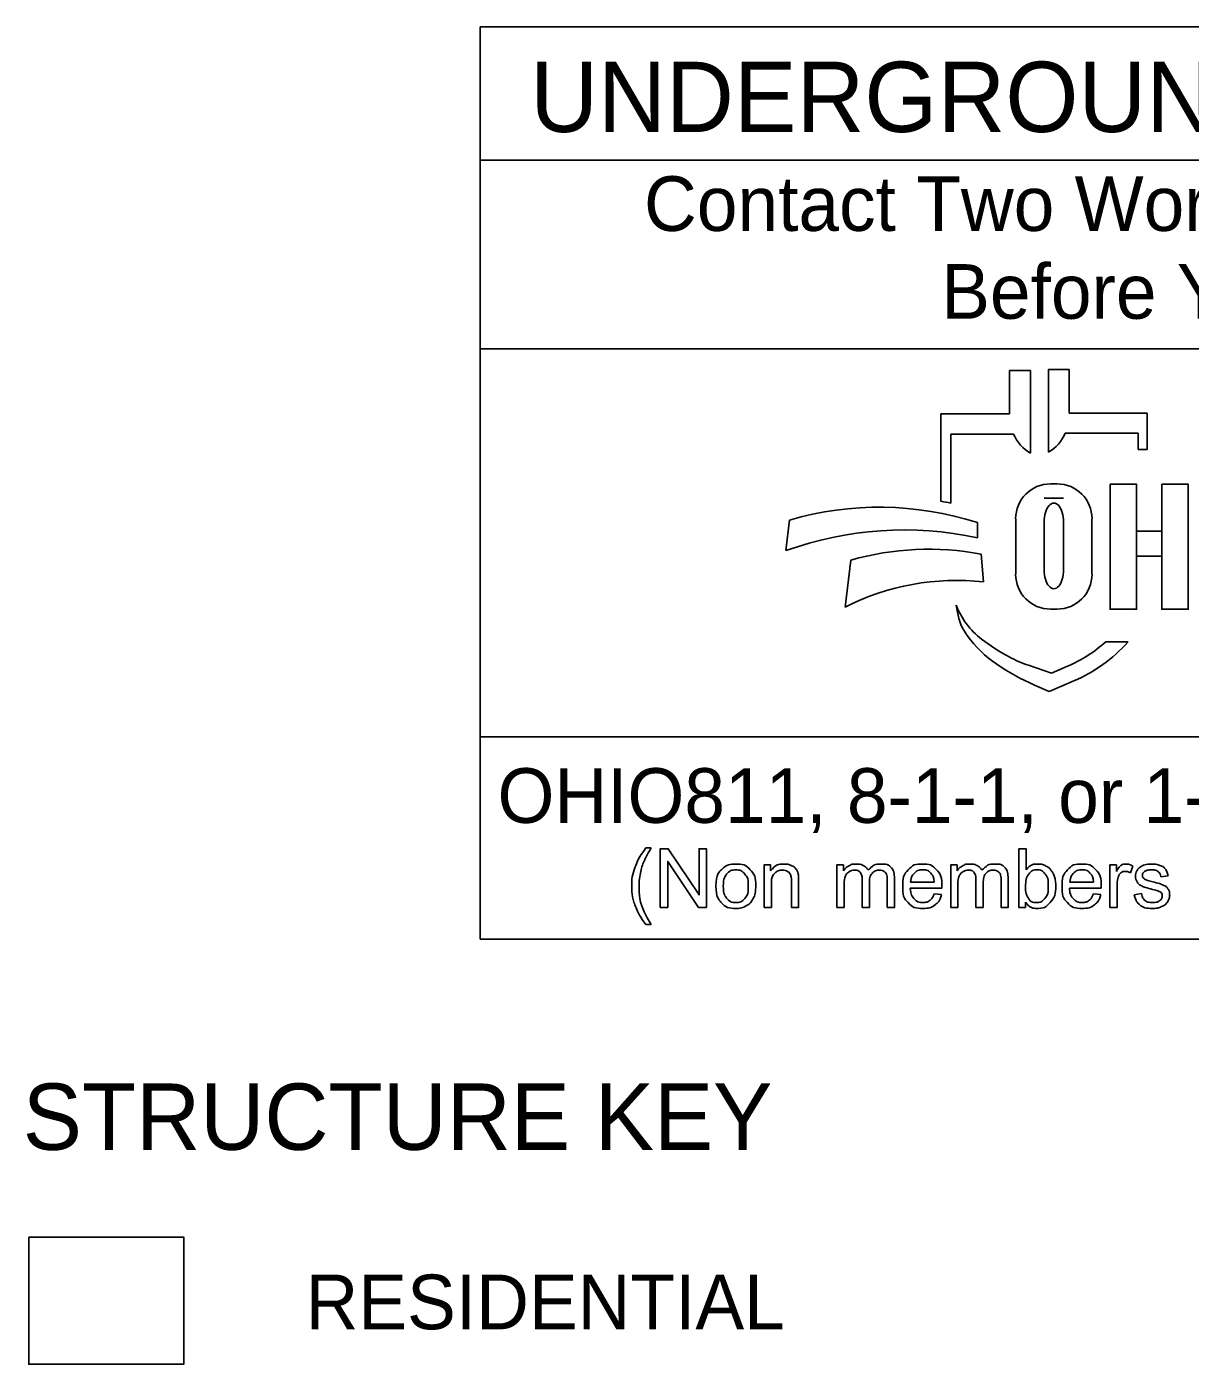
# Model space of a CAD drawing. Extents: x -8.8 to 41.4, y 0 to 34.6.
# Drawn here: x 20.008 to 22.988, y 5.453 to 8.88 of the extents above; entities that cross this region are included whole.
import ezdxf

# ---------------------------------------------------------------- set-up
doc = ezdxf.new("R2010")
doc.units = 0
doc.layers.add('SH_Border', color=7, linetype='Continuous')
doc.layers.add('SH_Data', color=7, linetype='Continuous')

msp = doc.modelspace()

# ---------------------------------------------------------------- linework, layer by layer
at = {"layer": 'SH_Border'}
for p, q in [((21.1696, 6.5424), (21.1696, 8.8799)), ((25.4196, 8.8799), (21.1696, 8.8799)), ((21.1696, 8.5383), (25.4196, 8.5383)), ((21.1696, 8.055), (25.4196, 8.055)), ((25.4196, 7.0603), (21.1696, 7.0603)), ((25.4196, 6.5424), (21.1696, 6.5424))]:
    msp.add_line(p, q, dxfattribs=at)
at = {"layer": 'SH_Data'}
for p, q in [((22.5256, 7.8879), (22.5256, 7.9994)), ((22.5256, 7.9994), (22.5793, 7.9994)), ((22.5793, 7.9994), (22.5793, 7.7873)), ((22.625, 7.7897), (22.625, 8.0017)), ((22.625, 8.0017), (22.6786, 8.0017)), ((22.6786, 8.0017), (22.6786, 7.8902)), ((22.3497, 7.664), (22.3497, 7.8879)), ((22.3497, 7.8879), (22.5256, 7.8879)), ((22.6786, 7.8902), (22.8778, 7.8902)), ((22.8778, 7.8902), (22.8778, 7.7964)), ((22.3749, 7.8365), (22.3749, 7.6596)), ((22.536, 7.8365), (22.3749, 7.8365)), ((22.8545, 7.8388), (22.6682, 7.8388)), ((22.8545, 7.7964), (22.8545, 7.8388)), ((22.8778, 7.7964), (22.8545, 7.7964)), ((22.6306, 7.7087), (22.6472, 7.7087)), ((22.6639, 7.6717), (22.6141, 7.6717)), ((21.9523, 7.5377), (21.9617, 7.6159)), ((22.443, 7.6094), (22.443, 7.5705)), ((22.5412, 7.4773), (22.5412, 7.6193)), ((22.6141, 7.4886), (22.6141, 7.611)), ((22.6639, 7.611), (22.6639, 7.4886)), ((22.7366, 7.6193), (22.7366, 7.4773)), ((22.1041, 7.3932), (22.1188, 7.5133)), ((22.4529, 7.5288), (22.4592, 7.4578)), ((22.3918, 7.3803), (22.3888, 7.3982)), ((22.6472, 7.3878), (22.6306, 7.3878)), ((22.7721, 7.3044), (22.8295, 7.3044)), ((22.5737, 7.244), (22.6331, 7.2236)), ((22.6331, 7.2236), (22.6742, 7.2414)), ((22.6904, 7.204), (22.6271, 7.1765)), ((22.6271, 7.1765), (22.5897, 7.193))]:
    msp.add_line(p, q, dxfattribs=at)
for points in [[(22.7831, 7.7077), (22.851, 7.7077), (22.851, 7.3877), (22.7831, 7.3877)], [(22.9152, 7.7077), (22.9832, 7.7077), (22.9832, 7.3877), (22.9152, 7.3877)], [(22.851, 7.5878), (22.9152, 7.5878), (22.9152, 7.5238), (22.851, 7.5238)], [(20.0133, 5.779), (20.4103, 5.779), (20.4103, 5.4532), (20.0133, 5.4532)]]:
    msp.add_lwpolyline(points, close=True, dxfattribs=at)
for points in [[(21.5942, 6.7762), (21.6074, 6.7762)], [(21.631, 6.6235), (21.631, 6.7737), (21.6513, 6.7737), (21.7303, 6.6558), (21.7303, 6.7737), (21.7493, 6.7737), (21.7493, 6.6235), (21.729, 6.6235), (21.65, 6.7415), (21.65, 6.6235), (21.631, 6.6235)], [(22.5664, 6.6235), (22.5494, 6.6235), (22.5494, 6.7737), (22.5678, 6.7737), (22.5678, 6.7202)], [(21.8969, 6.6235), (21.8969, 6.7324), (21.9135, 6.7324), (21.9135, 6.7169)], [(22.0833, 6.6235), (22.0833, 6.7324), (22.0998, 6.7324), (22.0998, 6.717)], [(22.3747, 6.6235), (22.3747, 6.7324), (22.3912, 6.7324), (22.3912, 6.717)], [(22.7825, 6.6235), (22.7825, 6.7324), (22.7991, 6.7324), (22.7991, 6.7159)], [(22.8416, 6.7289), (22.8351, 6.7118)], [(21.9154, 6.6829), (21.9154, 6.6235), (21.8969, 6.6235)], [(21.9853, 6.6904), (21.9853, 6.6235), (21.9669, 6.6235), (21.9669, 6.6897)], [(22.1664, 6.6867), (22.1664, 6.6235), (22.148, 6.6235), (22.148, 6.6942)], [(22.2309, 6.6982), (22.2309, 6.6235), (22.2124, 6.6235), (22.2124, 6.692)], [(22.272, 6.6883), (22.3327, 6.6883)], [(22.4578, 6.6867), (22.4578, 6.6235), (22.4394, 6.6235), (22.4394, 6.6942)], [(22.5222, 6.6982), (22.5222, 6.6235), (22.5038, 6.6235), (22.5038, 6.692)], [(22.68, 6.6883), (22.7407, 6.6883)], [(22.9315, 6.7042), (22.9134, 6.7018)], [(22.1018, 6.68), (22.1018, 6.6235), (22.0833, 6.6235)], [(22.3521, 6.6732), (22.2709, 6.6732)], [(22.3325, 6.6587), (22.3516, 6.6563)], [(22.3931, 6.68), (22.3931, 6.6235), (22.3747, 6.6235)], [(22.7601, 6.6732), (22.6789, 6.6732)], [(22.7405, 6.6587), (22.7596, 6.6563)], [(22.8009, 6.6805), (22.8009, 6.6235), (22.7825, 6.6235)], [(22.8451, 6.656), (22.8633, 6.6589)], [(22.5664, 6.6372), (22.5664, 6.6235)], [(21.6074, 6.5794), (21.5942, 6.5794)]]:
    msp.add_lwpolyline(points, dxfattribs=at)
for centre, radius, start, end in [((22.6274, 7.8732), 0.0985, 201.9296, 240.7469), ((22.5768, 7.8756), 0.0985, 299.2531, 338.0704), ((22.6306, 7.6193), 0.0895, 90, 180), ((22.6472, 7.6193), 0.0895, 0, 90), ((22.1918, 6.8298), 0.8191, 72.1402, 106.3144), ((22.2216, 6.8551), 0.8191, 79.2074, 81.0007), ((22.2549, 6.6987), 0.8919, 77.8238, 109.8274), ((22.3188, 6.809), 0.7322, 79.44, 105.8467), ((22.6306, 7.4773), 0.0895, 180, 270), ((22.6472, 7.4773), 0.0895, 270, 0), ((22.3908, 6.8258), 0.6357, 83.8248, 116.8021), ((22.5762, 7.4703), 0.2008, 201.0457, 232.5314), ((22.5331, 7.4044), 0.1433, 189.6817, 216.0884), ((22.6668, 7.5018), 0.3088, 216.0884, 235.7167), ((22.7687, 7.7215), 0.5173, 232.5314, 241.794), ((22.5308, 7.5718), 0.3602, 293.4582, 312.0712), ((22.5308, 7.5718), 0.401, 293.4582, 317.8286), ((22.6835, 7.5627), 0.3371, 241.794, 250.9821), ((22.8333, 7.7461), 0.6044, 235.7167, 246.2325)]:
    msp.add_arc(centre, radius, start, end, dxfattribs=at)
for centre, start_param, end_param in [((22.639, 7.611), 4.712389, 7.853982), ((22.639, 7.4886), 1.570796, 4.712389)]:
    msp.add_ellipse(centre, major_axis=(0, 0.0484), ratio=0.514403, start_param=start_param, end_param=end_param, dxfattribs=at)
for points in [[(21.5942, 6.5794), (21.579, 6.5986), (21.5684, 6.6244), (21.5578, 6.6502), (21.5578, 6.6779), (21.5578, 6.7023), (21.5657, 6.7246), (21.575, 6.7505), (21.5942, 6.7762)], [(21.6074, 6.7762), (21.595, 6.7549), (21.591, 6.7458), (21.5848, 6.7317), (21.5812, 6.7163), (21.5768, 6.6972), (21.5768, 6.6778), (21.5768, 6.6285), (21.6074, 6.5794)], [(21.7734, 6.678), (21.7734, 6.7082), (21.7902, 6.7227), (21.8043, 6.7348), (21.8244, 6.7348), (21.8468, 6.7348), (21.8611, 6.7201), (21.8753, 6.7054), (21.8753, 6.6795), (21.8753, 6.6585), (21.869, 6.6465), (21.8627, 6.6345), (21.8507, 6.6278), (21.8387, 6.6211), (21.8244, 6.6211), (21.8016, 6.6211), (21.7875, 6.6358), (21.7734, 6.6504), (21.7734, 6.678)], [(21.7924, 6.678), (21.7924, 6.6571), (21.8015, 6.6467), (21.8106, 6.6363), (21.8244, 6.6363), (21.8381, 6.6363), (21.8472, 6.6467), (21.8563, 6.6572), (21.8563, 6.6786), (21.8563, 6.6988), (21.8472, 6.7092), (21.838, 6.7196), (21.8244, 6.7196), (21.8106, 6.7196), (21.8015, 6.7092), (21.7924, 6.6989), (21.7924, 6.678)], [(21.9135, 6.7169), (21.9255, 6.7348), (21.9481, 6.7348), (21.958, 6.7348), (21.9662, 6.7313), (21.9744, 6.7277), (21.9785, 6.722), (21.9826, 6.7162), (21.9843, 6.7084), (21.9853, 6.7032), (21.9853, 6.6904)], [(21.9669, 6.6897), (21.9669, 6.7009), (21.9647, 6.7065), (21.9626, 6.7121), (21.9571, 6.7154), (21.9516, 6.7188), (21.9442, 6.7188), (21.9325, 6.7188), (21.9239, 6.7113), (21.9154, 6.7038), (21.9154, 6.6829)], [(22.0998, 6.717), (22.1049, 6.725), (22.1135, 6.7299), (22.122, 6.7348), (22.1328, 6.7348), (22.1449, 6.7348), (22.1526, 6.7298), (22.1604, 6.7247), (22.1636, 6.7157), (22.1765, 6.7348), (22.1972, 6.7348), (22.2134, 6.7348), (22.2221, 6.7258), (22.2309, 6.7169), (22.2309, 6.6982)], [(22.148, 6.6942), (22.148, 6.7065), (22.1435, 6.7126), (22.139, 6.7188), (22.1287, 6.7188), (22.1209, 6.7188), (22.1143, 6.7147), (22.1077, 6.7106), (22.1047, 6.7027), (22.1018, 6.6948), (22.1018, 6.68)], [(22.2124, 6.692), (22.2124, 6.7031), (22.2106, 6.708), (22.2088, 6.7128), (22.2041, 6.7158), (22.1994, 6.7188), (22.1931, 6.7188), (22.1816, 6.7188), (22.174, 6.7111), (22.1664, 6.7035), (22.1664, 6.6867)], [(22.3516, 6.6563), (22.3471, 6.6396), (22.3349, 6.6304), (22.3227, 6.6211), (22.3038, 6.6211), (22.2799, 6.6211), (22.2659, 6.6358), (22.2519, 6.6505), (22.2519, 6.677), (22.2519, 6.7045), (22.2661, 6.7196), (22.2802, 6.7348), (22.3027, 6.7348), (22.3245, 6.7348), (22.3384, 6.7199), (22.3522, 6.7051), (22.3522, 6.6781), (22.3522, 6.6765), (22.3521, 6.6732)], [(22.3327, 6.6883), (22.3315, 6.7021), (22.3258, 6.709), (22.317, 6.7197), (22.3029, 6.7197), (22.2902, 6.7197), (22.2815, 6.7111), (22.2729, 6.7026), (22.272, 6.6883)], [(22.3912, 6.717), (22.3963, 6.725), (22.4048, 6.7299), (22.4133, 6.7348), (22.4242, 6.7348), (22.4363, 6.7348), (22.444, 6.7298), (22.4518, 6.7247), (22.4549, 6.7157), (22.4679, 6.7348), (22.4886, 6.7348), (22.5048, 6.7348), (22.5135, 6.7258), (22.5222, 6.7169), (22.5222, 6.6982)], [(22.4394, 6.6942), (22.4394, 6.7065), (22.4349, 6.7126), (22.4304, 6.7188), (22.4201, 6.7188), (22.4123, 6.7188), (22.4057, 6.7147), (22.3991, 6.7106), (22.3961, 6.7027), (22.3931, 6.6948), (22.3931, 6.68)], [(22.5038, 6.692), (22.5038, 6.7031), (22.502, 6.708), (22.5002, 6.7128), (22.4955, 6.7158), (22.4908, 6.7188), (22.4844, 6.7188), (22.473, 6.7188), (22.4654, 6.7111), (22.4578, 6.7035), (22.4578, 6.6867)], [(22.5662, 6.6788), (22.5662, 6.6592), (22.5715, 6.6505), (22.5802, 6.6363), (22.595, 6.6363), (22.6071, 6.6363), (22.6159, 6.6468), (22.6247, 6.6573), (22.6247, 6.6781), (22.6247, 6.6994), (22.6162, 6.7095), (22.6078, 6.7197), (22.5958, 6.7197), (22.5838, 6.7197), (22.575, 6.7092), (22.5662, 6.6987), (22.5662, 6.6788)], [(22.5678, 6.7202), (22.5795, 6.7348), (22.5976, 6.7348), (22.6076, 6.7348), (22.6166, 6.7307), (22.6256, 6.7267), (22.6313, 6.7194), (22.6371, 6.7121), (22.6404, 6.7017), (22.6437, 6.6914), (22.6437, 6.6796), (22.6437, 6.6517), (22.6298, 6.6364), (22.616, 6.6211), (22.5967, 6.6211), (22.5774, 6.6211), (22.5664, 6.6372)], [(22.7596, 6.6563), (22.7551, 6.6396), (22.7429, 6.6304), (22.7307, 6.6211), (22.7117, 6.6211), (22.6879, 6.6211), (22.6739, 6.6358), (22.6599, 6.6505), (22.6599, 6.677), (22.6599, 6.7045), (22.6741, 6.7196), (22.6882, 6.7348), (22.7107, 6.7348), (22.7325, 6.7348), (22.7464, 6.7199), (22.7602, 6.7051), (22.7602, 6.6781), (22.7602, 6.6765), (22.7601, 6.6732)], [(22.7407, 6.6883), (22.7395, 6.7021), (22.7338, 6.709), (22.7249, 6.7197), (22.7109, 6.7197), (22.6982, 6.7197), (22.6895, 6.7111), (22.6809, 6.7026), (22.68, 6.6883)], [(22.7991, 6.7159), (22.8054, 6.7274), (22.8108, 6.7311), (22.8162, 6.7348), (22.8226, 6.7348), (22.8319, 6.7348), (22.8416, 6.7289)], [(22.9134, 6.7018), (22.9122, 6.7102), (22.9063, 6.715), (22.9004, 6.7197), (22.8896, 6.7197), (22.8769, 6.7197), (22.8715, 6.7155), (22.866, 6.7113), (22.866, 6.7056), (22.866, 6.702), (22.8683, 6.6992), (22.8706, 6.6962), (22.8754, 6.6942), (22.8781, 6.6932), (22.8917, 6.6895), (22.9113, 6.6843), (22.919, 6.681), (22.9268, 6.6776), (22.9312, 6.6713), (22.9356, 6.6649), (22.9356, 6.6555), (22.9356, 6.6463), (22.9302, 6.6382), (22.9248, 6.63), (22.9147, 6.6256), (22.9045, 6.6211), (22.8917, 6.6211), (22.8704, 6.6211), (22.8593, 6.6299), (22.8482, 6.6388), (22.8451, 6.656)], [(22.8633, 6.6589), (22.8648, 6.6479), (22.8719, 6.6421), (22.8789, 6.6363), (22.8916, 6.6363), (22.9043, 6.6363), (22.9105, 6.6414), (22.9166, 6.6466), (22.9166, 6.6536), (22.9166, 6.6598), (22.9112, 6.6634), (22.9074, 6.6659), (22.8923, 6.6697), (22.872, 6.6748), (22.8641, 6.6785), (22.8563, 6.6823), (22.8522, 6.6889), (22.8482, 6.6955), (22.8482, 6.7035), (22.8482, 6.7107), (22.8515, 6.7169), (22.8549, 6.7231), (22.8606, 6.7272), (22.8649, 6.7304), (22.8724, 6.7326), (22.8798, 6.7348), (22.8883, 6.7348), (22.9011, 6.7348), (22.9108, 6.7311), (22.9205, 6.7274), (22.9251, 6.7211), (22.9298, 6.7148), (22.9315, 6.7042)], [(22.8351, 6.7118), (22.8284, 6.7158), (22.8216, 6.7158), (22.8156, 6.7158), (22.8108, 6.7122), (22.806, 6.7085), (22.804, 6.7021), (22.8009, 6.6922), (22.8009, 6.6805)], [(22.2709, 6.6732), (22.272, 6.6553), (22.2811, 6.6458), (22.2902, 6.6363), (22.3038, 6.6363), (22.314, 6.6363), (22.3212, 6.6416), (22.3283, 6.647), (22.3325, 6.6587)], [(22.6789, 6.6732), (22.68, 6.6553), (22.6891, 6.6458), (22.6982, 6.6363), (22.7118, 6.6363), (22.722, 6.6363), (22.7291, 6.6416), (22.7363, 6.647), (22.7405, 6.6587)]]:
    msp.add_open_spline(points, degree=3, dxfattribs=at)

# ---------------------------------------------------------------- texts
for s, height, p in [('UNDERGROUND UTILITIES', 0.18, (21.2978, 8.6103)), ('Contact Two Working Days', 0.14, (21.5893, 8.3568)), ('Before You Dig', 0.14, (22.3504, 8.1318)), ('OHIO811, 8-1-1, or 1-800-362-2764', 0.14, (21.2141, 6.8402)), ('STRUCTURE KEY', 0.17, (19.998, 6.0025)), ('RESIDENTIAL', 0.14, (20.7223, 5.5428))]:
    msp.add_text(s, height=height, dxfattribs=at).set_placement(p)

doc.saveas('drawing.dxf')
